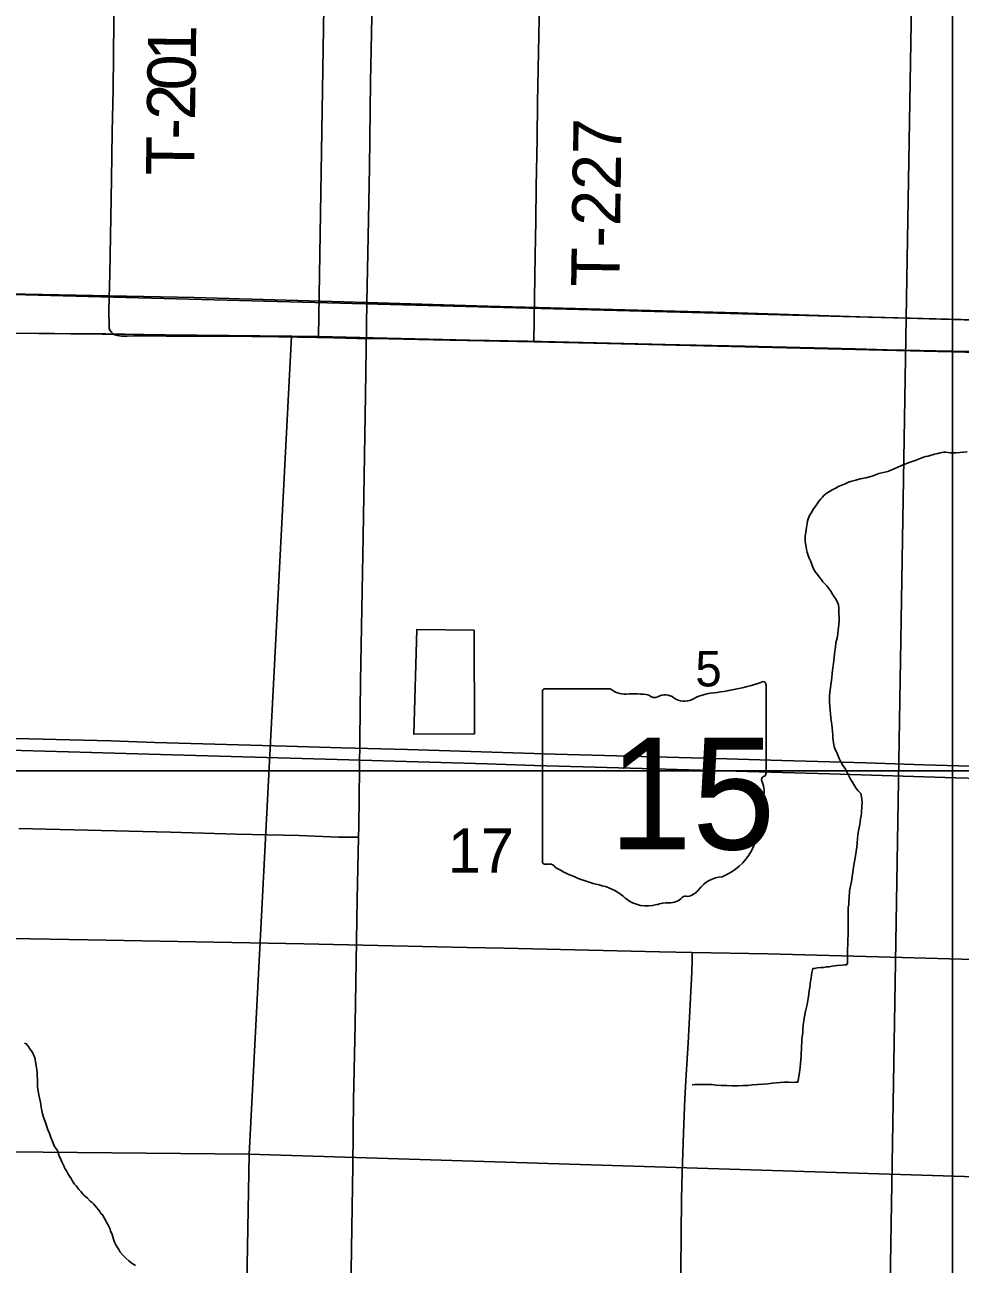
# Model space of a CAD drawing. Extents: x 0 to 68, y 0 to 52.9.
# Drawn here: x 44.57 to 45.735, y 34.125 to 35.667 of the extents above; entities that cross this region are included whole.
import ezdxf

# ---------------------------------------------------------------- set-up
doc = ezdxf.new("R2010")
doc.units = 0
for name, color, linetype in [('Default', 7, 'Continuous'), ('GM_X_County_Road', 7, 'Continuous'), ('GM_X_Minor_Lake', 7, 'Continuous'), ('GM_X_Minor_River', 7, 'Continuous'), ('GM_X_State_Route', 7, 'Continuous'), ('GM_X_State_Shield', 7, 'Continuous'), ('GM_X_Township', 7, 'Continuous'), ('GM_X_Township_Road', 7, 'Continuous'), ('GM_X_Township_Road_Text', 7, 'Continuous')]:
    doc.layers.add(name, color=color, linetype=linetype)

msp = doc.modelspace()

# ---------------------------------------------------------------- linework, layer by layer
at = {"layer": 'Default'}
for p, q in [((45.7251, 32.7683), (45.7251, 42.0083)), ((42.2581, 34.7391), (49.6501, 34.7391))]:
    msp.add_line(p, q, dxfattribs=at)
for points in [[(44.3441, 36.6667), (45.6896, 36.6248), (45.6672, 35.3023), (44.3202, 35.3382)], [(45.6896, 36.6248), (47.0429, 36.5865), (47.008, 35.2636), (45.6672, 35.3023)], [(43.9027, 36.3407), (44.9528, 36.3285), (44.9359, 35.2797), (44.9023, 35.2801), (43.8802, 35.2907)], [(46.0139, 36.3013), (45.9997, 35.2541), (45.9809, 35.2543), (44.9359, 35.2797), (44.9528, 36.3285)], [(44.3202, 35.3382), (45.6672, 35.3023), (45.6451, 33.9748), (44.3032, 34.0046)], [(45.6672, 35.3023), (47.008, 35.2636), (46.979, 33.9387), (45.6451, 33.9748)], [(43.8802, 35.2907), (44.9023, 35.2801), (44.8493, 34.2618), (43.8665, 34.2714)], [(44.9023, 35.2801), (44.9359, 35.2797), (45.9809, 35.2543), (45.9257, 34.2283), (44.8493, 34.2618)], [(43.8665, 34.2714), (44.8493, 34.2618), (44.8302, 33.199), (44.3286, 33.2092), (43.8561, 33.2057), (43.8657, 34.2406)], [(44.8493, 34.2618), (45.9257, 34.2283), (45.9077, 33.1703), (44.8302, 33.199)]]:
    msp.add_lwpolyline(points, close=True, dxfattribs=at)
at = {"layer": 'GM_X_County_Road'}
for points in [[(44.3255, 34.5342), (44.3272, 34.5341), (44.363, 34.5335), (44.6485, 34.5287), (44.9175, 34.5237), (45.1209, 34.519), (45.1669, 34.5181), (45.3604, 34.5135), (45.4008, 34.5128)], [(45.4008, 34.5128), (45.4949, 34.5113), (45.6327, 34.5073), (45.7507, 34.504), (45.9246, 34.4984), (45.9302, 34.4983), (45.9411, 34.498)]]:
    msp.add_lwpolyline(points, dxfattribs=at)
at = {"layer": 'GM_X_Minor_Lake'}
for points in [[(45.1295, 34.914), (45.058, 34.9149), (45.0543, 34.7846)], [(45.1295, 34.914), (45.058, 34.9149), (45.0543, 34.7846), (45.1299, 34.785), (45.1295, 34.914)], [(45.0543, 34.7846), (45.1299, 34.785), (45.1295, 34.914)]]:
    msp.add_lwpolyline(points, dxfattribs=at)
at = {"layer": 'GM_X_Minor_River'}
for points in [[(45.743, 35.1359), (45.7294, 35.1348), (45.7258, 35.1348), (45.7222, 35.1348), (45.7194, 35.1352), (45.7165, 35.1356), (45.7141, 35.1356), (45.7117, 35.1352), (45.7097, 35.1348), (45.7065, 35.134), (45.7025, 35.1329), (45.6973, 35.1313), (45.6945, 35.1305), (45.6917, 35.1301), (45.6888, 35.1293), (45.686, 35.1281), (45.6828, 35.1269), (45.6784, 35.1253), (45.6736, 35.1237), (45.6676, 35.1213), (45.6607, 35.1185), (45.6531, 35.1154), (45.6446, 35.1114), (45.6334, 35.109), (45.625, 35.1058), (45.6169, 35.1038), (45.6101, 35.1022), (45.6045, 35.1007), (45.5997, 35.0995), (45.5953, 35.0983), (45.5912, 35.0963), (45.5872, 35.0943), (45.5828, 35.0927), (45.5796, 35.0907), (45.576, 35.0891)], [(45.576, 35.0891), (45.5728, 35.0871), (45.5691, 35.0851), (45.5667, 35.0831), (45.5647, 35.0815), (45.5631, 35.0795), (45.5611, 35.0775), (45.5591, 35.0751), (45.5571, 35.0723), (45.5546, 35.0687), (45.5518, 35.0651), (45.5494, 35.0603), (45.547, 35.0567), (45.5454, 35.0527), (45.5446, 35.0495), (45.5442, 35.0467), (45.5433, 35.0419), (45.5417, 35.0306), (45.5417, 35.0274), (45.5417, 35.0242), (45.5421, 35.0218), (45.5429, 35.0178), (45.5433, 35.0146), (45.5441, 35.011), (45.5453, 35.0069), (45.5469, 35.0029), (45.5485, 34.9993), (45.5501, 34.9945), (45.5521, 34.9905), (45.5545, 34.9864), (45.5569, 34.9832), (45.5601, 34.9788), (45.5621, 34.9764), (45.5637, 34.974), (45.5661, 34.9716), (45.5685, 34.9691), (45.5709, 34.9659), (45.5733, 34.9627), (45.5757, 34.9587), (45.5777, 34.9555), (45.5801, 34.9523), (45.5817, 34.9486), (45.5829, 34.9454), (45.5833, 34.941), (45.5836, 34.9382), (45.5836, 34.9342), (45.584, 34.931), (45.584, 34.9262), (45.5836, 34.9205), (45.5828, 34.9145), (45.582, 34.9093), (45.5812, 34.9041), (45.5799, 34.8981), (45.5791, 34.8929), (45.5783, 34.888), (45.5779, 34.884), (45.5775, 34.8804), (45.5771, 34.8764), (45.5767, 34.8728), (45.5763, 34.8696), (45.5759, 34.8672), (45.5755, 34.864), (45.575, 34.86), (45.5746, 34.8551), (45.5722, 34.8363), (45.5718, 34.8315), (45.5718, 34.8279), (45.5717, 34.8239), (45.5721, 34.8194), (45.5725, 34.8146), (45.5729, 34.8098), (45.5733, 34.805), (45.5741, 34.8014), (45.5749, 34.7966), (45.5753, 34.7921), (45.5757, 34.7881), (45.5761, 34.7837), (45.5761, 34.7805), (45.5765, 34.7769), (45.5769, 34.7741), (45.5772, 34.7713), (45.5776, 34.7693), (45.5784, 34.7668), (45.5792, 34.7648), (45.5804, 34.7628), (45.582, 34.7584), (45.584, 34.7544), (45.586, 34.75), (45.5884, 34.7455), (45.5912, 34.7419), (45.5932, 34.7379), (45.5956, 34.7335), (45.598, 34.7287), (45.6008, 34.7242), (45.6032, 34.7198), (45.6056, 34.7166), (45.6076, 34.7142), (45.6108, 34.7106), (45.612, 34.7041), (45.6124, 34.6993), (45.612, 34.6953)], [(45.612, 34.6953), (45.612, 34.6925), (45.6116, 34.6901), (45.6116, 34.6869), (45.6112, 34.6829), (45.6103, 34.6793), (45.6099, 34.6752), (45.6091, 34.67), (45.6083, 34.6664), (45.6079, 34.6644), (45.6075, 34.6616), (45.6071, 34.6588), (45.6067, 34.6548), (45.6063, 34.6488), (45.6059, 34.6444), (45.605, 34.6387), (45.6042, 34.6331), (45.603, 34.6263), (45.6018, 34.6191), (45.601, 34.6127), (45.6001, 34.6071), (45.5993, 34.6014), (45.5981, 34.5954), (45.5969, 34.589), (45.5965, 34.5814), (45.5957, 34.5766), (45.5957, 34.5726), (45.5952, 34.5689), (45.5952, 34.5649), (45.5952, 34.5617), (45.5952, 34.5585), (45.5952, 34.5549), (45.5952, 34.5501), (45.5952, 34.5453), (45.5952, 34.54), (45.5952, 34.5352), (45.5948, 34.5288), (45.5947, 34.5248), (45.5947, 34.5216), (45.5943, 34.5184), (45.5943, 34.5156), (45.5943, 34.5116), (45.5943, 34.5083), (45.5943, 34.5051), (45.5943, 34.5023), (45.5943, 34.4995), (45.5931, 34.4975), (45.5911, 34.4975), (45.5871, 34.4971), (45.5818, 34.4967), (45.5778, 34.4964), (45.575, 34.496), (45.5714, 34.4952), (45.5682, 34.4948), (45.5646, 34.494), (45.561, 34.494), (45.5569, 34.4936), (45.5529, 34.4928), (45.5509, 34.4928), (45.5497, 34.488), (45.5489, 34.4812), (45.5477, 34.4744), (45.5473, 34.4692), (45.5464, 34.4656), (45.546, 34.4611), (45.5452, 34.4555), (45.544, 34.4483), (45.542, 34.4399), (45.5399, 34.4287), (45.5391, 34.4218), (45.5387, 34.4174), (45.5387, 34.4142), (45.5383, 34.4098), (45.5375, 34.4058), (45.5375, 34.401), (45.5371, 34.3962), (45.537, 34.3921), (45.5366, 34.3881), (45.5366, 34.3841), (45.5362, 34.3793), (45.5358, 34.3745), (45.5354, 34.3701), (45.535, 34.3669), (45.5346, 34.3637), (45.5342, 34.3613), (45.5329, 34.3536), (45.5325, 34.3516), (45.5301, 34.3516), (45.5261, 34.3512), (45.5213, 34.3513), (45.5157, 34.3513), (45.5105, 34.3509), (45.506, 34.3505), (45.5008, 34.3501), (45.4952, 34.3493), (45.4892, 34.349), (45.482, 34.3486), (45.4759, 34.3482), (45.4703, 34.3474), (45.4643, 34.3474), (45.4583, 34.347)], [(44.5698, 34.4002), (44.5718, 34.399)], [(44.5718, 34.399), (44.5746, 34.3957), (44.5762, 34.3933), (44.5782, 34.3909), (44.5798, 34.3884), (44.5805, 34.3864), (44.5817, 34.384), (44.5825, 34.3816), (44.5848, 34.3699), (44.5852, 34.3667), (44.5855, 34.363), (44.5855, 34.3594), (44.5859, 34.3554), (44.5858, 34.351), (44.5862, 34.3458), (44.5869, 34.3401), (44.5877, 34.3357), (44.5884, 34.3321), (44.5892, 34.3284), (44.59, 34.324), (44.5907, 34.32), (44.5915, 34.316), (44.5923, 34.3119), (44.5934, 34.3079), (44.595, 34.3035), (44.5966, 34.2986), (44.5985, 34.2934), (44.6009, 34.2877), (44.6028, 34.2825), (44.6048, 34.2776), (44.6071, 34.2712), (44.6107, 34.2663), (44.6127, 34.2607), (44.615, 34.2554), (44.6166, 34.2514), (44.6186, 34.2474), (44.6201, 34.2441), (44.6221, 34.2409), (44.6237, 34.2377), (44.6257, 34.2344), (44.6277, 34.2316), (44.6296, 34.2284), (44.632, 34.2247), (44.634, 34.2223), (44.6356, 34.2203), (44.6376, 34.2178), (44.64, 34.2154), (44.6415, 34.2134), (44.6435, 34.2109), (44.6459, 34.2093), (44.6483, 34.2069), (44.6515, 34.2032), (44.6539, 34.2016), (44.6559, 34.2), (44.6583, 34.1971), (44.6634, 34.1906), (44.665, 34.1882), (44.6674, 34.1858), (44.6682, 34.1838), (44.6706, 34.1797), (44.6721, 34.1765), (44.6737, 34.1745), (44.6753, 34.1712), (44.6765, 34.1684), (44.6768, 34.166), (44.678, 34.164), (44.6788, 34.1619), (44.6796, 34.1591), (44.6804, 34.1559), (44.6819, 34.1523), (44.6835, 34.149), (44.6855, 34.1458), (44.6871, 34.1434), (44.6891, 34.1397), (44.6922, 34.1361), (44.6958, 34.1324), (44.6998, 34.1292), (44.7038, 34.1259), (44.7078, 34.1231)], [(45.4583, 34.347), (45.4511, 34.3471), (45.4442, 34.3475), (45.4374, 34.3475), (45.4306, 34.3479), (45.425, 34.3484), (45.4189, 34.3484), (45.4117, 34.3484), (45.4073, 34.3484), (45.4041, 34.3484), (45.4013, 34.348), (45.4013, 34.348), (45.4009, 34.348)]]:
    msp.add_lwpolyline(points, dxfattribs=at)
at = {"layer": 'GM_X_State_Route'}
for points in [[(44.3142, 34.7718), (44.3195, 34.7716), (44.4769, 34.7669), (44.6244, 34.7626), (44.7391, 34.7591), (44.9588, 34.753), (45.1457, 34.7475), (45.2047, 34.7455), (45.2801, 34.7436), (45.5719, 34.7351), (45.7292, 34.7304), (45.8341, 34.7274)], [(44.5415, 34.7798), (44.6774, 34.7761), (44.7319, 34.7742), (44.8958, 34.7696), (44.9646, 34.7677), (45.0465, 34.7653), (45.2302, 34.7598), (45.4303, 34.7542), (45.5123, 34.7518), (45.6169, 34.7488), (45.6893, 34.7463), (45.7616, 34.7445)]]:
    msp.add_lwpolyline(points, dxfattribs=at)
at = {"layer": 'GM_X_State_Shield'}
for p, q in [((45.2144, 34.8375), (45.2144, 34.6262)), ((45.2987, 34.8412), (45.2171, 34.8412)), ((45.4928, 34.7359), (45.4928, 34.8464)), ((45.4928, 34.7359), (45.4928, 34.7359))]:
    msp.add_line(p, q, dxfattribs=at)
for centre, radius, start, end in [((45.3936, 35.1293), 0.2953, 275.8445, 288.9065), ((45.4897, 34.8469), 0.0031, 351.8621, 97.738), ((45.2176, 34.838), 0.00323, 98.1301, 188.1301), ((45.3181, 34.8657), 0.0313, 231.6195, 271.1119), ((45.3285, 34.7225), 0.1123, 80.4867, 94.9883), ((45.354, 34.8391), 0.00903, 219.7921, 297.1024), ((45.3672, 34.8147), 0.0188, 54.4667, 119.1411), ((45.4313, 34.7766), 0.0594, 97.3462, 120.7689), ((45.3914, 34.8482), 0.0226, 233.8562, 294.8282), ((45.4921, 34.7278), 0.0048, 107.944, 210.337), ((45.4616, 34.7138), 0.0288, 340.033, 23.6496), ((45.4895, 34.7354), 0.00332, 289.6038, 7.7341), ((45.5039, 34.6896), 0.021, 136.8065, 186.9296), ((45.4102, 34.6755), 0.0739, 292.3089, 8.9858), ((45.2176, 34.6258), 0.00325, 171.9584, 258.3066), ((45.2181, 34.6474), 0.0248, 267.339, 280.6039), ((45.2232, 34.614), 0.00895, 29.7484, 93.2717), ((45.3362, 34.8039), 0.2132, 240.4129, 257.1985), ((45.4413, 34.5669), 0.0404, 94.4031, 142.5768), ((45.2727, 34.5313), 0.0667, 47.1842, 75.836), ((45.3901, 34.6057), 0.0239, 282.8732, 323.2771), ((45.3448, 34.613), 0.0423, 230.7004, 286.2918), ((45.3693, 34.5399), 0.0348, 85.6951, 111.2099), ((45.3724, 34.5972), 0.0226, 268.777, 315.5493), ((45.3928, 34.5767), 0.00635, 65.7517, 132.6484)]:
    msp.add_arc(centre, radius, start, end, dxfattribs=at)
at = {"layer": 'GM_X_Township'}
for points in [[(45.9849, 35.2547), (45.1961, 35.2737), (44.6712, 35.2829), (44.0303, 35.2868), (44.0257, 35.2866), (43.8798, 35.2893), (43.8838, 35.4287), (43.8855, 35.4776), (43.8856, 35.4836), (43.8943, 35.8214)], [(43.8255, 31.1431), (43.8412, 32.1252), (43.8416, 32.1514), (43.848, 32.6506), (43.8484, 32.6776), (43.8577, 33.1798), (43.8583, 33.2049), (43.8631, 33.7395), (43.8693, 34.2426), (43.8728, 34.5425), (43.8742, 34.7352), (43.8773, 34.8686), (43.8737, 34.9229), (43.874, 34.9402), (43.8796, 35.1936), (43.8797, 35.2152), (43.8798, 35.2893), (44.0257, 35.2866), (44.0303, 35.2868), (44.6712, 35.2829), (45.1961, 35.2737), (45.9849, 35.2547)]]:
    msp.add_lwpolyline(points, dxfattribs=at)
at = {"layer": 'GM_X_Township_Road'}
for points in [[(44.6875, 36.3339), (44.6867, 36.2759), (44.6861, 36.2004), (44.6843, 36.0101), (44.6841, 35.9746), (44.6844, 35.9498), (44.6841, 35.9374), (44.6835, 35.8753), (44.6826, 35.8098), (44.6819, 35.7147), (44.681, 35.6721), (44.6801, 35.5868), (44.6791, 35.5343), (44.6782, 35.4752), (44.6759, 35.3571), (44.6748, 35.3122), (44.6751, 35.2929), (44.6753, 35.2898), (44.6759, 35.2876), (44.6781, 35.2848)], [(45.2038, 35.2728), (45.2053, 35.3808), (45.2061, 35.4235), (45.2066, 35.4661), (45.208, 35.5252), (45.2085, 35.5711), (45.2108, 35.6958), (45.2116, 35.745), (45.2124, 35.7843), (45.2134, 35.8762), (45.214, 35.9451), (45.2146, 36.0106), (45.2156, 36.0792), (45.2165, 36.1709), (45.217, 36.2038), (45.2173, 36.2394), (45.2183, 36.2811), (45.2189, 36.3254)], [(44.9961, 35.3218), (44.9975, 35.4038), (44.9991, 35.4899), (45.0003, 35.5966), (45.0062, 35.8796), (45.0077, 35.9698), (45.008, 35.9847)], [(43.1062, 35.3458), (43.1156, 35.3456), (43.1197, 35.3455), (43.2469, 35.3466), (43.3905, 35.347), (43.5013, 35.3478), (43.6325, 35.3489), (43.7474, 35.3477), (43.9935, 35.3431), (44.0673, 35.342), (44.2273, 35.339), (44.4652, 35.3342), (44.7811, 35.3281), (44.9961, 35.3218)], [(44.9855, 34.6564), (44.9858, 34.6696), (44.9879, 34.8501), (44.9915, 35.0306), (44.9941, 35.2069), (44.9961, 35.3218)], [(44.9961, 35.3218), (45.1461, 35.3173), (45.4577, 35.3088), (45.6095, 35.3042), (45.8309, 35.298), (45.9212, 35.2959), (45.9745, 35.2946), (46.2041, 35.2879), (46.4584, 35.2808), (46.524, 35.2791), (46.7127, 35.2736), (46.9998, 35.266), (47.0091, 35.2658)], [(44.6781, 35.2848), (44.6809, 35.2822), (44.6854, 35.2806), (44.6905, 35.2801), (44.6974, 35.2801), (44.7134, 35.2803), (44.7461, 35.28), (44.8166, 35.2798), (44.9249, 35.2787), (44.984, 35.2771), (45.0233, 35.2767), (45.0791, 35.2755), (45.2038, 35.2728)], [(45.2038, 35.2728), (45.2595, 35.2715), (45.3252, 35.2702), (45.4662, 35.2673), (45.604, 35.2641), (45.6434, 35.2631), (45.7451, 35.2607), (45.8303, 35.2586), (45.9091, 35.2567), (45.9747, 35.2553), (45.9832, 35.255)], [(44.5629, 34.667), (44.6654, 34.6647), (44.7516, 34.6628), (44.8336, 34.6601), (44.9116, 34.6583), (44.9608, 34.6565), (44.9772, 34.6565), (44.9855, 34.6564)], [(44.9746, 33.9909), (44.9752, 34.0297), (44.977, 34.1446), (44.9784, 34.2471), (44.9794, 34.3292), (44.9816, 34.4235), (44.9839, 34.5794), (44.9855, 34.6564)], [(45.3804, 33.7162), (45.3826, 33.8421), (45.3849, 34.0095), (45.3856, 34.0587), (45.3866, 34.1178), (45.3877, 34.2064), (45.3885, 34.2392), (45.3902, 34.2884), (45.3917, 34.331), (45.3934, 34.3605), (45.3961, 34.3998), (45.4004, 34.4883), (45.4007, 34.5047), (45.4008, 34.5128)]]:
    msp.add_lwpolyline(points, dxfattribs=at)

# ---------------------------------------------------------------- texts
at = {"layer": 'Default'}
for s, height, p in [('5', 0.0442, (45.4048, 34.844)), ('17', 0.05525, (45.0968, 34.612))]:
    msp.add_text(s, height=height, rotation=0, dxfattribs=at).set_placement(p)
at = {"layer": 'GM_X_State_Shield'}
msp.add_text('15', height=0.13922, dxfattribs=at).set_placement((45.2973, 34.6411))
at = {"layer": 'GM_X_Township_Road_Text'}
for s, rotation, p in [('1', 89.3234, (44.7831, 35.6223)), ('0', 89.3038, (44.7826, 35.5856)), ('2', 89.031, (44.782, 35.5487)), ('-', 89.0088, (44.7816, 35.5242)), ('T-227', 89.1595, (45.3101, 35.341)), ('T', 89.1131, (44.7809, 35.4795))]:
    msp.add_text(s, height=0.06, rotation=rotation, dxfattribs=at).set_placement(p)

doc.saveas('drawing.dxf')
